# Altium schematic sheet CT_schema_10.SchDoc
size 386 x 278 mm
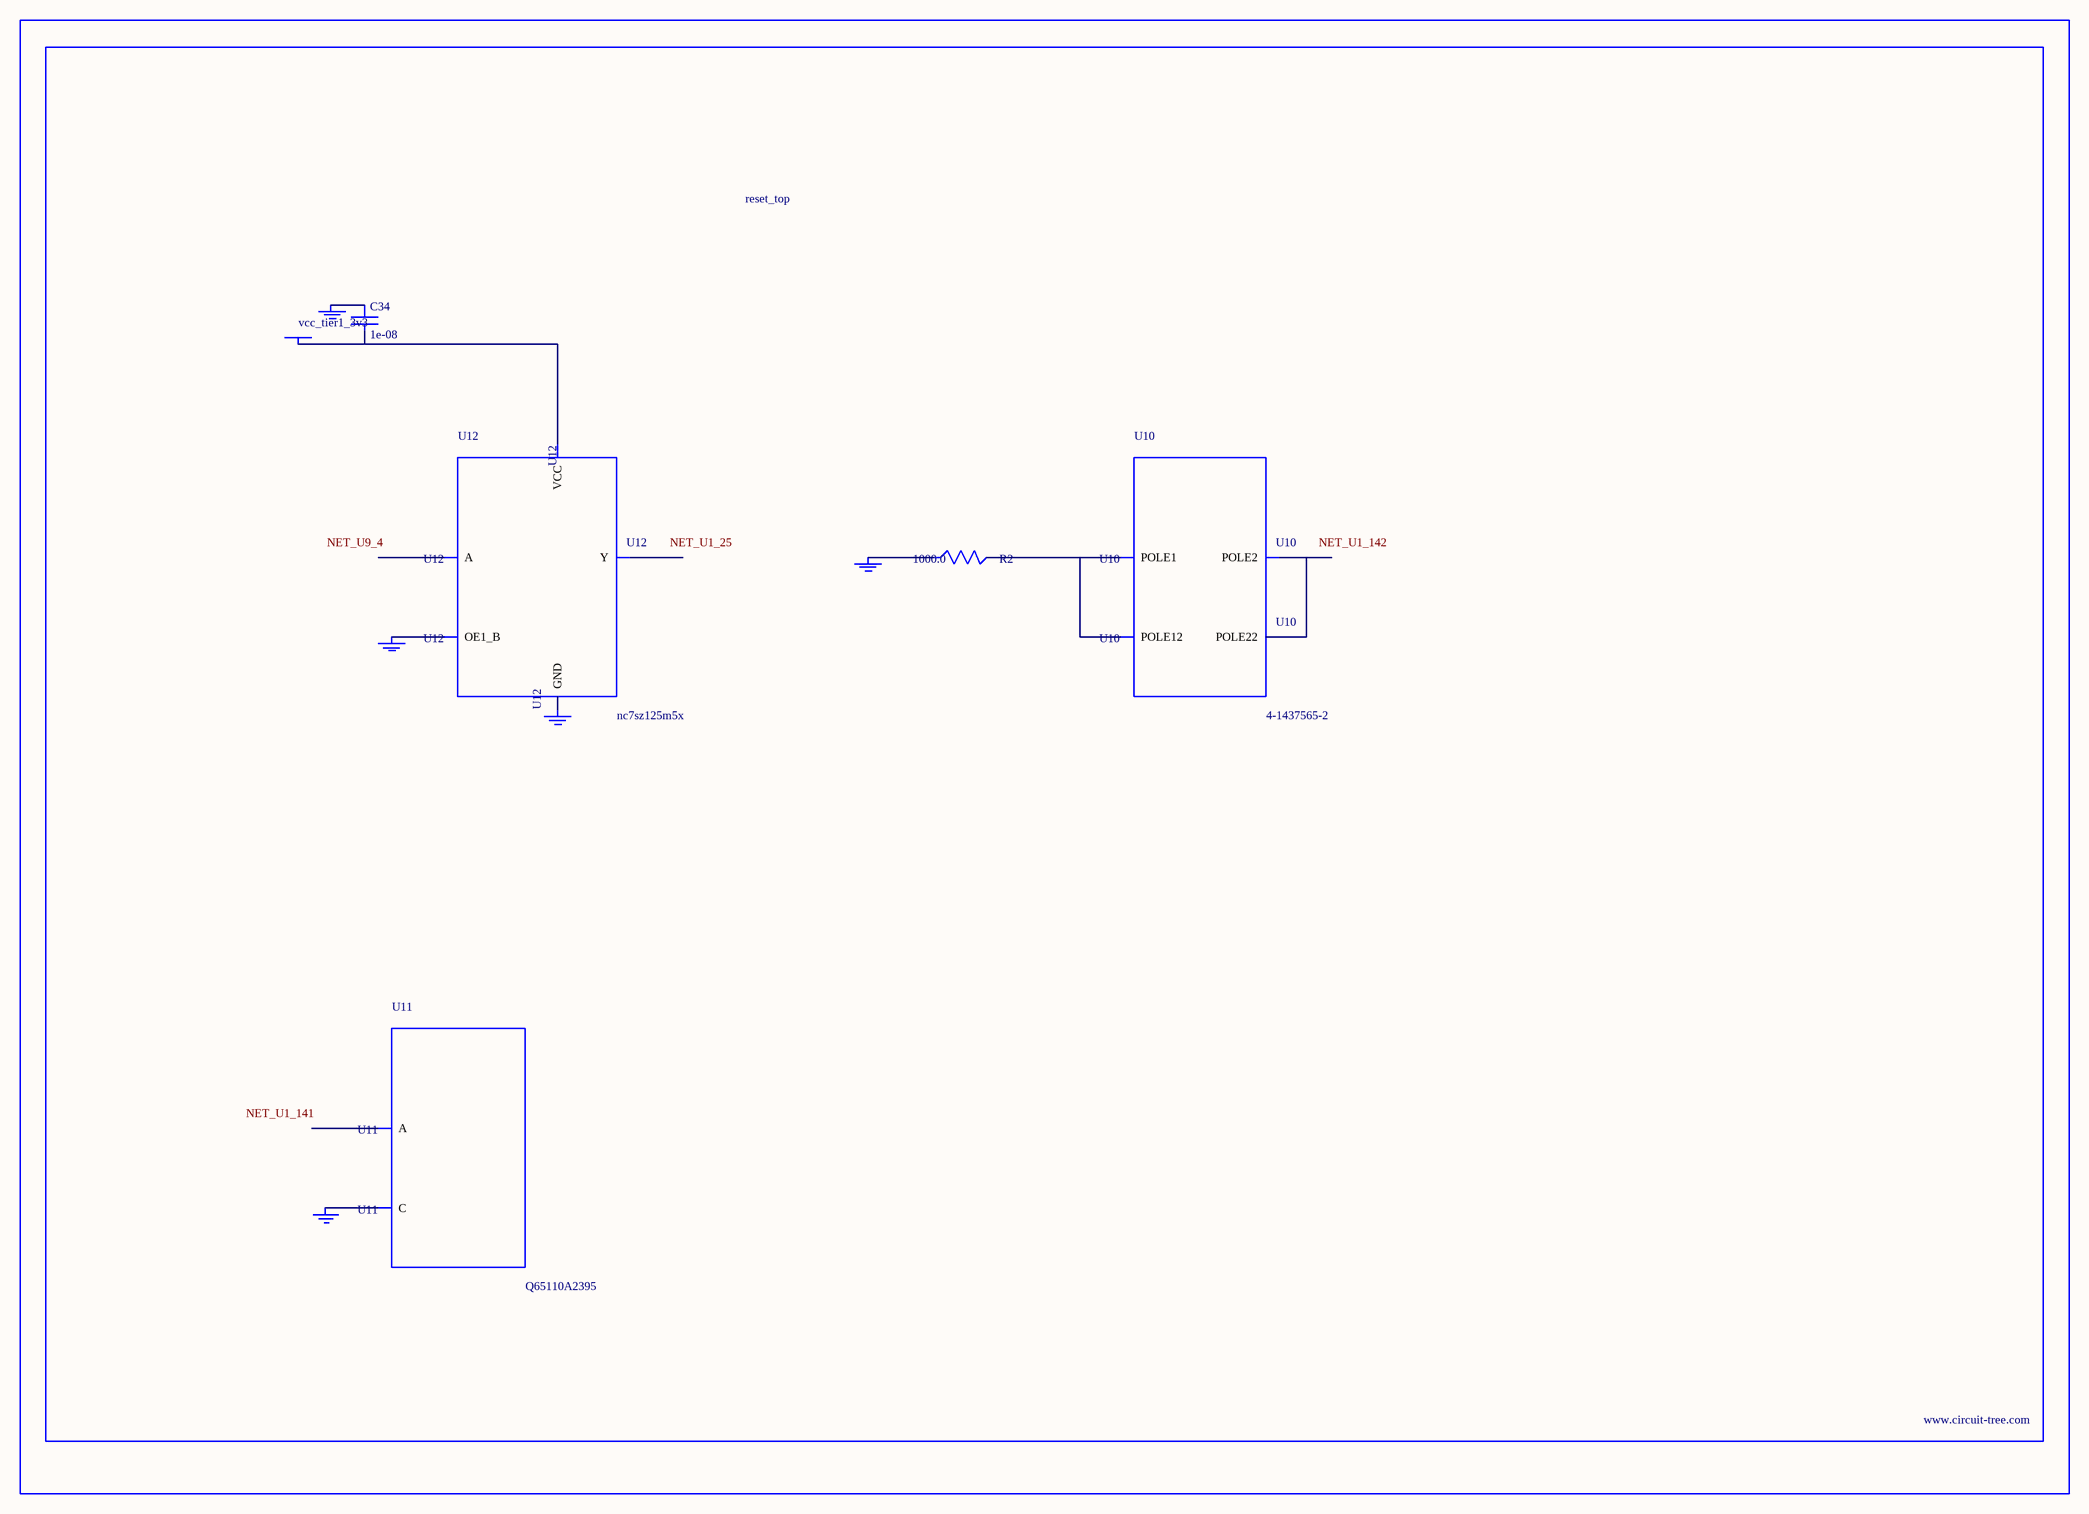
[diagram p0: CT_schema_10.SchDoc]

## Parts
BORDER9  (no value)
C34  1e-08  [C0402]
GND_INSTANCE_9_0  (no value)
GND_INSTANCE_9_1  (no value)
GND_INSTANCE_9_2  (no value)
GND_INSTANCE_9_3  (no value)
GND_INSTANCE_9_4  (no value)
POWER_INSTANCE_9_0  vcc_tier1_3v3
R2  1000.0  [R0603]
U10  4-1437565-2  [SW_4-1437565-2]
U11  Q65110A2395  [LGM67K-G1J2-24-Z]
U12  nc7sz125m5x  [NC7SZ125M5X]

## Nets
NetC34_1: C34.1 GND_INSTANCE_9_2.0(GND)
NetC34_2: C34.2 POWER_INSTANCE_9_0.0(PWR) U12.5(VCC)
NetGND_INSTANCE_9_0_0: GND_INSTANCE_9_0.0(GND) R2.1
NetGND_INSTANCE_9_1_0: GND_INSTANCE_9_1.0(GND) U11.C
NetGND_INSTANCE_9_3_0: GND_INSTANCE_9_3.0(GND) U12.1(OE1_B)
NetGND_INSTANCE_9_4_0: GND_INSTANCE_9_4.0(GND) U12.3(GND)
NetR2_2: R2.2 U10.1(POLE1) U10.2(POLE12)
NetU10_3: U10.3(POLE2) U10.4(POLE22)

Not connected (* = marked no-connect by the designer): U11 A; U12 2(A) 4(Y)

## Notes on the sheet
- Labels drawn without touching a wire or pin: NET_U1_25, NET_U1_141, NET_U1_142, NET_U9_4

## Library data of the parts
BORDER9 = BORDER_PAGE9
C34 = C0402C103K3RAC
GND_INSTANCE_9_0-GND_INSTANCE_9_4 = GND
POWER_INSTANCE_9_0 = PWR
R2 = RC0603JR-071KL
